// Mitsubishi GX Works2 project: BT-LR01 Read data   PLC: Q03UDV

PROGRAM 00-MAIN
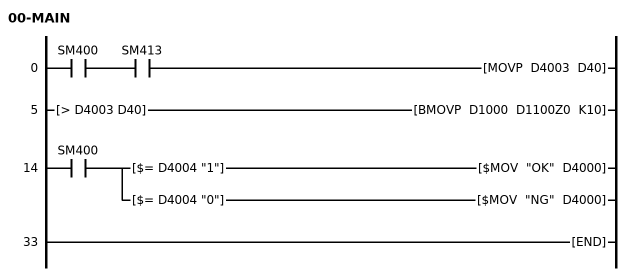
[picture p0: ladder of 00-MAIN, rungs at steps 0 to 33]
0     LD      SM400
      AND     SM413
      MOVP    D4003 D40
5     LD>     D4003 D40
      BMOVP   D1000 D1100Z0 K10
14    LD      SM400
      MPS
      AND$=   D4004 "1"
      $MOV    "OK" D4000
      MPP
      AND$=   D4004 "0"
      $MOV    "NG" D4000
33    END
END_PROGRAM

PROGRAM 01-Time  // Inittial
0     END
END_PROGRAM
